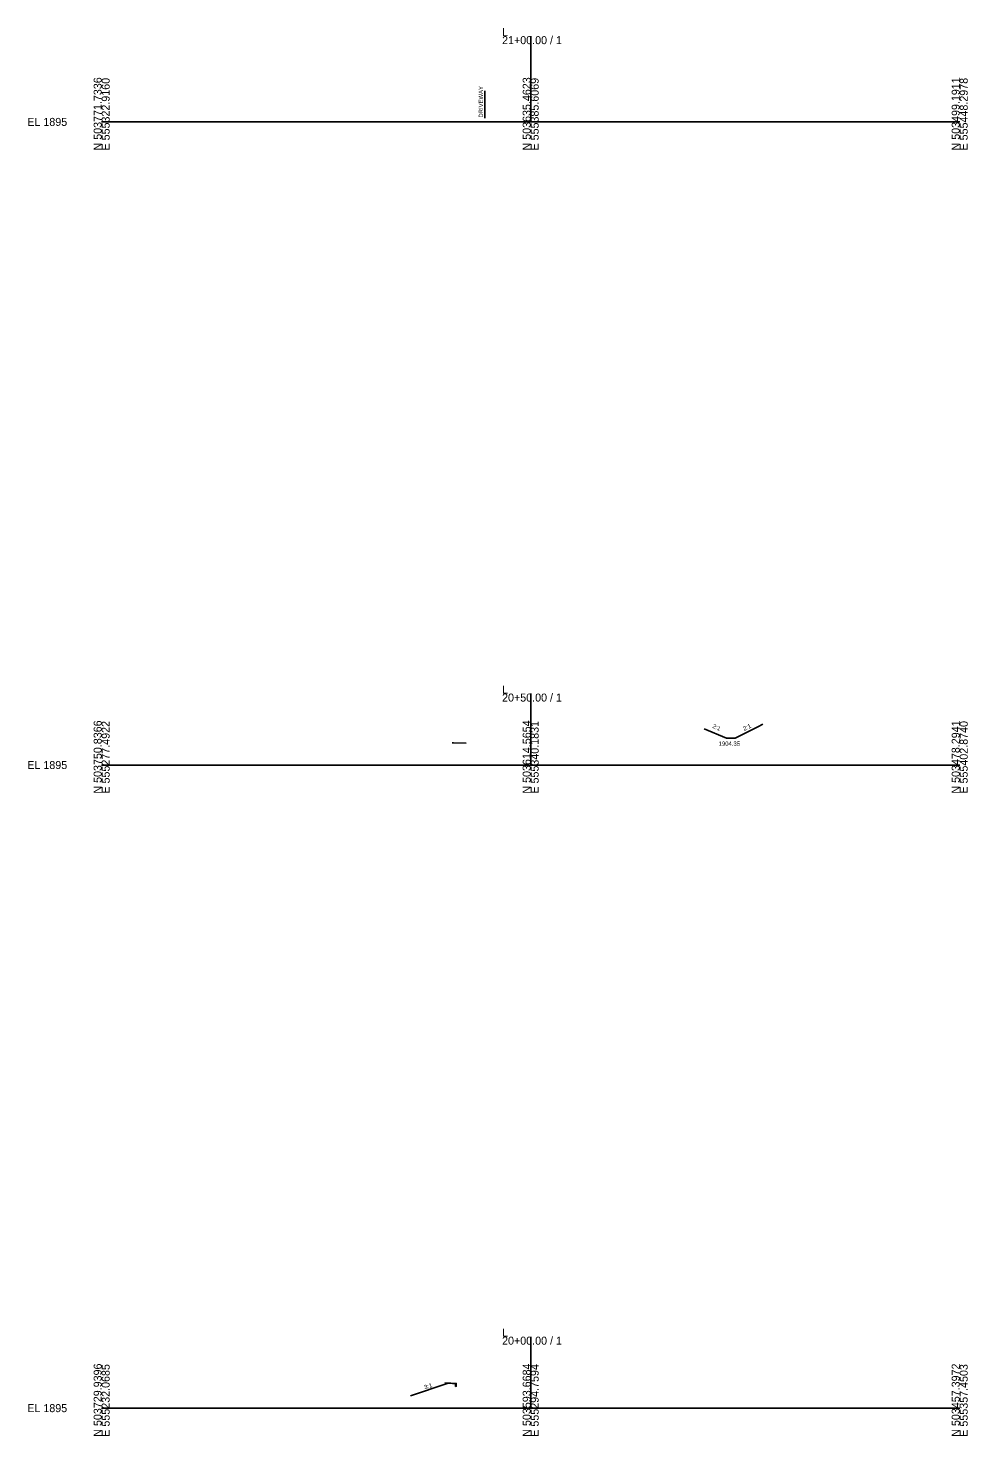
# Model space of a CAD drawing. Extents: x -26 to 3303, y -10 to 4703.
# Drawn here: x 474.3 to 802.8, y -9.7 to 482.8 of the extents above; entities that cross this region are included whole.
import ezdxf

# ---------------------------------------------------------------- set-up
doc = ezdxf.new("R2010")
doc.units = 0
for name, color, linetype in [('Exist Cross Section Cell', 7, 'Continuous'), ('Prop CMT Shear Line', 7, 'Continuous'), ('Prop XS Ditch Slope Text', 7, 'Continuous'), ('Prop XS Finish Grade', 7, 'Continuous'), ('Prop XS Label Text', 7, 'Continuous'), ('Scratch_Level_0', 7, 'Continuous'), ('Scratch_Level_4', 7, 'Continuous')]:
    doc.layers.add(name, color=color, linetype=linetype)

msp = doc.modelspace()

# ---------------------------------------------------------------- linework, layer by layer
at = {"layer": 'Exist Cross Section Cell'}
for p, q in [((650, 450), (650, 480)), ((500, 450), (650, 450)), ((650, 450), (800, 450)), ((650, 225), (650, 250)), ((500, 225), (650, 225)), ((650, 225), (800, 225)), ((650, 0), (650, 25)), ((500, 0), (650, 0)), ((650, 0), (800, 0))]:
    msp.add_line(p, q, dxfattribs=at)
at = {"layer": 'Prop XS Finish Grade'}
for points in [[(710.66, 237.64), (718.48, 234.35), (718.48, 234.35)], [(731.21, 239.28), (729.45, 238.39), (721.49, 234.37)], [(718.48, 234.35), (718.48, 234.35), (718.48, 234.35), (718.48, 234.35), (718.48, 234.35), (718.48, 234.35), (721.49, 234.37)]]:
    msp.add_lwpolyline(points, dxfattribs=at)
at = {"layer": 'Scratch_Level_0'}
msp.add_line((634, 451.33), (634, 460.82), dxfattribs=at)
for points in [[(607.98, 4.33), (621.19, 8.74)], [(621.19, 8.74), (622.66, 8.65), (623.76, 8.63)], [(624, 8.23), (623.96, 8.13), (623.96, 8.41), (623.96, 8.63), (623.79, 8.63), (623.76, 8.63), (623.76, 8.19), (623.76, 7.61), (624, 7.65), (624, 7.65), (624, 8.23), (624, 8.23), (624, 8.23)]]:
    msp.add_lwpolyline(points, dxfattribs=at)
at = {"layer": 'Scratch_Level_4'}
for points in [[(622.5, 232.8), (622.99, 232.79), (627.5, 232.7)], [(620.04, 8.82), (621.23, 8.75), (622.12, 8.72)]]:
    msp.add_lwpolyline(points, dxfattribs=at)

# ---------------------------------------------------------------- texts
at = {"layer": 'Exist Cross Section Cell'}
for s, p in [('L', (640, 480)), ('21+00.00 / 1', (640, 477.2)), ('EL 1895', (474, 448.6)), ('L', (640, 250)), ('20+50.00 / 1', (640, 247.2)), ('EL 1895', (474, 223.6)), ('20+00.00 / 1', (640, 22.2)), ('L', (640, 25)), ('EL 1895', (474, -1.4))]:
    msp.add_text(s, height=2.8, dxfattribs=at).set_placement(p)
for s, p in [('N 503771.7336', (500, 440)), ('E 555322.9160', (502.8, 440)), ('N 503635.4623', (650, 440)), ('E 555385.6069', (652.8, 440)), ('N 503499.1911', (800, 440)), ('E 555448.2978', (802.8, 440)), ('N 503750.8366', (500, 215)), ('E 555277.4922', (502.8, 215)), ('N 503614.5654', (650, 215)), ('E 555340.1831', (652.8, 215)), ('N 503478.2941', (800, 215)), ('E 555402.8740', (802.8, 215)), ('N 503729.9396', (500, -10)), ('E 555232.0685', (502.8, -10)), ('N 503593.6684', (650, -10)), ('E 555294.7594', (652.8, -10)), ('N 503457.3972', (800, -10)), ('E 555357.4503', (802.8, -10))]:
    msp.add_text(s, height=2.8, rotation=90, dxfattribs=at).set_placement(p)
at = {"layer": 'Prop CMT Shear Line'}
msp.add_text('X', height=0.0025, dxfattribs=at).set_placement((718.48, 234.35))
at = {"layer": 'Prop XS Ditch Slope Text'}
msp.add_text('1904.35', height=1.5, dxfattribs=at).set_placement((715.72, 231.73))
at = {"layer": 'Prop XS Label Text'}
for rotation, p in [(334.5107, (713.41, 238.11)), (25.4893, (724.68, 236.93))]:
    msp.add_text('2:1', height=1.5, rotation=rotation, dxfattribs=at).set_placement(p)
at = {"layer": 'Scratch_Level_0'}
for s, rotation, p in [('DRIVEWAY', 90, (633.33, 451.51)), ('3:1', 18.4332, (613.01, 6.52))]:
    msp.add_text(s, height=1.5, rotation=rotation, dxfattribs=at).set_placement(p)
for p in [(623.96, 8.13), (624, 8.23)]:
    msp.add_text('X', height=0.0025, dxfattribs=at).set_placement(p)

doc.saveas('drawing.dxf')
